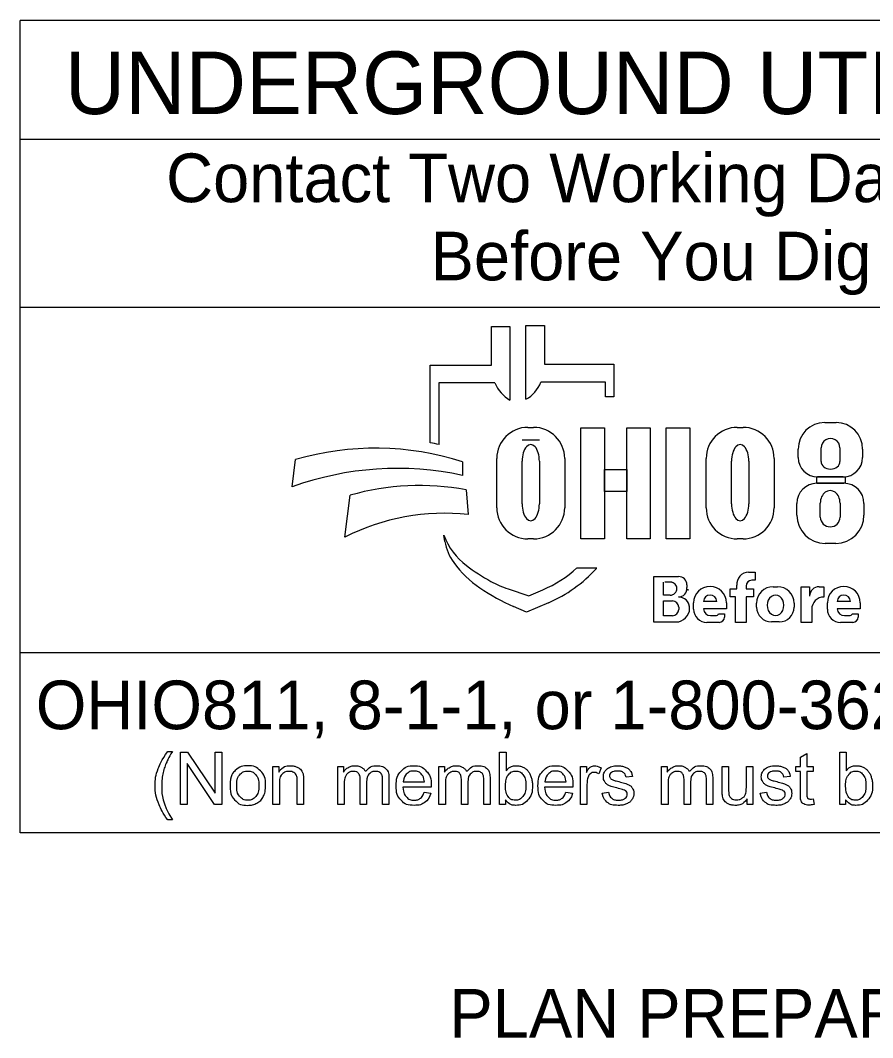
# Model space of a CAD drawing. Extents: x -7.9 to 76.1, y 0 to 22.
# Drawn here: x 46.508 to 48.961, y 2.433 to 5.36 of the extents above; entities that cross this region are included whole.
import ezdxf

# ---------------------------------------------------------------- set-up
doc = ezdxf.new("R2010")
doc.units = 0
doc.layers.add('SH_Data', color=7, linetype='Continuous')
doc.layers.add('SH_Text', color=7, linetype='Continuous')

msp = doc.modelspace()

# ---------------------------------------------------------------- linework, layer by layer
at = {"layer": 'SH_Data'}
for p, q in [((46.5077, 3.0228), (46.5077, 5.3603)), ((50.7577, 5.3603), (46.5077, 5.3603)), ((46.5077, 5.0187), (50.7577, 5.0187)), ((46.5077, 4.5353), (50.7577, 4.5353)), ((50.7577, 3.5406), (46.5077, 3.5406)), ((50.7577, 3.0228), (46.5077, 3.0228))]:
    msp.add_line(p, q, dxfattribs=at)
at = {"layer": 'SH_Text'}
for p, q in [((47.8638, 4.3683), (47.8638, 4.4798)), ((47.8638, 4.4798), (47.9174, 4.4798)), ((47.9174, 4.4798), (47.9174, 4.2677)), ((47.9631, 4.27), (47.9631, 4.4821)), ((47.9631, 4.4821), (48.0167, 4.4821)), ((48.0167, 4.4821), (48.0167, 4.3706)), ((47.6878, 4.1444), (47.6878, 4.3683)), ((47.6878, 4.3683), (47.8638, 4.3683)), ((48.0167, 4.3706), (48.216, 4.3706)), ((48.216, 4.3706), (48.216, 4.2768)), ((47.713, 4.3168), (47.713, 4.14)), ((47.8742, 4.3168), (47.713, 4.3168)), ((48.1927, 4.3192), (48.0063, 4.3192)), ((48.1927, 4.2768), (48.1927, 4.3192)), ((48.216, 4.2768), (48.1927, 4.2768)), ((47.9688, 4.1891), (47.9853, 4.1891)), ((48.5718, 4.1891), (48.5883, 4.1891)), ((48.8233, 4.2031), (48.8561, 4.2031)), ((48.002, 4.1521), (47.9522, 4.1521)), ((48.8132, 4.0911), (48.8132, 4.1304)), ((48.8673, 4.1304), (48.8673, 4.0911)), ((47.8793, 3.9576), (47.8793, 4.0996)), ((48.0748, 4.0996), (48.0748, 3.9576)), ((48.4823, 3.9576), (48.4823, 4.0996)), ((48.6778, 4.0996), (48.6778, 3.9576)), ((48.747, 4.1025), (48.747, 4.1268)), ((48.9324, 4.1268), (48.9324, 4.1025)), ((47.2904, 4.0181), (47.2998, 4.0962)), ((47.7811, 4.0897), (47.7811, 4.0509)), ((47.9522, 3.969), (47.9522, 4.0914)), ((48.002, 4.0914), (48.002, 3.969)), ((48.5552, 3.969), (48.5552, 4.0914)), ((48.605, 4.0914), (48.605, 3.969)), ((48.8764, 4.0465), (48.803, 4.0465)), ((48.8012, 4.0282), (48.8785, 4.0282)), ((47.4423, 3.8736), (47.457, 3.9937)), ((47.7911, 4.0091), (47.7973, 3.9382)), ((48.7433, 3.9363), (48.7433, 3.9703)), ((48.8108, 3.9303), (48.8108, 3.9712)), ((48.8677, 3.9712), (48.8677, 3.9303)), ((48.9364, 3.9703), (48.9364, 3.9363)), ((47.73, 3.8607), (47.7269, 3.8786)), ((47.9853, 3.8682), (47.9688, 3.8682)), ((48.5883, 3.8682), (48.5718, 3.8682)), ((48.8555, 3.8553), (48.8243, 3.8553)), ((48.1103, 3.7848), (48.1677, 3.7848)), ((48.3315, 3.629), (48.3315, 3.7598)), ((48.3315, 3.7598), (48.4027, 3.7598)), ((48.6041, 3.7726), (48.6236, 3.7726)), ((48.6236, 3.7491), (48.6134, 3.7491)), ((48.6236, 3.7726), (48.6236, 3.7496)), ((47.9118, 3.7244), (47.9712, 3.7039)), ((47.9712, 3.7039), (48.0123, 3.7217)), ((48.3595, 3.7063), (48.3595, 3.7432)), ((48.3847, 3.7432), (48.3634, 3.7432)), ((48.4265, 3.736), (48.4265, 3.7281)), ((48.5515, 3.7012), (48.5515, 3.7242)), ((48.5515, 3.7242), (48.5709, 3.7242)), ((48.5709, 3.7242), (48.5709, 3.7346)), ((48.597, 3.7326), (48.597, 3.7242)), ((48.597, 3.7242), (48.6185, 3.7242)), ((48.6185, 3.7242), (48.6185, 3.7012)), ((48.6753, 3.7307), (48.6875, 3.7307)), ((48.7556, 3.6278), (48.7556, 3.7305)), ((48.7556, 3.7305), (48.7801, 3.7305)), ((48.7801, 3.7305), (48.7801, 3.7036)), ((48.8074, 3.7305), (48.8213, 3.7305)), ((48.8213, 3.7305), (48.8213, 3.7009)), ((48.3789, 3.7063), (48.3595, 3.7063)), ((48.3595, 3.6469), (48.3595, 3.6897)), ((48.3595, 3.6897), (48.385, 3.6897)), ((48.5664, 3.7012), (48.5515, 3.7012)), ((48.5664, 3.6278), (48.5664, 3.7012)), ((48.6185, 3.7012), (48.597, 3.7012)), ((48.597, 3.7012), (48.597, 3.6278)), ((47.9652, 3.6569), (47.9279, 3.6734)), ((48.0285, 3.6844), (47.9652, 3.6569)), ((48.4032, 3.6716), (48.4032, 3.6652)), ((48.4345, 3.6687), (48.4345, 3.6684)), ((48.4461, 3.6658), (48.4461, 3.6842)), ((48.5127, 3.6882), (48.4741, 3.6882)), ((48.5406, 3.6666), (48.4742, 3.6666)), ((48.5406, 3.6842), (48.5406, 3.6666)), ((48.6275, 3.6721), (48.6275, 3.6829)), ((48.7353, 3.6829), (48.7353, 3.6721)), ((48.7861, 3.666), (48.7861, 3.6278)), ((48.831, 3.6658), (48.831, 3.6842)), ((48.8976, 3.6882), (48.8591, 3.6882)), ((48.9255, 3.6666), (48.8591, 3.6666)), ((48.9255, 3.6842), (48.9255, 3.6666)), ((48.3848, 3.6469), (48.3595, 3.6469)), ((48.4951, 3.6473), (48.5092, 3.6473)), ((48.5178, 3.6529), (48.5347, 3.6529)), ((48.5347, 3.6529), (48.5347, 3.6431)), ((48.88, 3.6473), (48.8942, 3.6473)), ((48.9027, 3.6529), (48.9196, 3.6529)), ((48.9196, 3.6529), (48.9196, 3.6431)), ((48.3952, 3.629), (48.3315, 3.629)), ((48.5195, 3.6278), (48.4841, 3.6278)), ((48.597, 3.6278), (48.5664, 3.6278)), ((48.6925, 3.6294), (48.6703, 3.6294)), ((48.7861, 3.6278), (48.7556, 3.6278)), ((48.9044, 3.6278), (48.869, 3.6278))]:
    msp.add_line(p, q, dxfattribs=at)
for points in [[(48.1212, 4.1881), (48.1891, 4.1881), (48.1891, 3.8681), (48.1212, 3.8681)], [(48.2533, 4.1881), (48.3213, 4.1881), (48.3213, 3.8681), (48.2533, 3.8681)], [(48.3666, 4.1881), (48.4354, 4.1881), (48.4354, 3.8681), (48.3666, 3.8681)], [(48.1891, 4.0682), (48.2533, 4.0682), (48.2533, 4.0042), (48.1891, 4.0042)], [(48.8009, 4.0465), (48.8825, 4.0465), (48.8825, 4.0281), (48.8009, 4.0281)]]:
    msp.add_lwpolyline(points, close=True, dxfattribs=at)
for points in [[(46.9323, 3.2566), (46.9455, 3.2566)], [(46.9691, 3.1039), (46.9691, 3.2541), (46.9894, 3.2541), (47.0684, 3.1361), (47.0684, 3.2541), (47.0874, 3.2541), (47.0874, 3.1039), (47.0671, 3.1039), (46.9881, 3.2218), (46.9881, 3.1039), (46.9691, 3.1039)], [(47.9045, 3.1039), (47.8875, 3.1039), (47.8875, 3.2541), (47.9059, 3.2541), (47.9059, 3.2006)], [(48.7535, 3.1358), (48.7535, 3.1984), (48.7399, 3.1984), (48.7399, 3.2128), (48.7535, 3.2128), (48.7535, 3.2397), (48.7719, 3.2508), (48.7719, 3.2128), (48.7903, 3.2128), (48.7903, 3.1984), (48.7719, 3.1984), (48.7719, 3.1347)], [(48.8836, 3.1039), (48.8666, 3.1039), (48.8666, 3.2541), (48.885, 3.2541), (48.885, 3.2006)], [(47.2351, 3.1039), (47.2351, 3.2128), (47.2516, 3.2128), (47.2516, 3.1973)], [(47.4215, 3.1039), (47.4215, 3.2128), (47.4379, 3.2128), (47.4379, 3.1974)], [(47.7128, 3.1039), (47.7128, 3.2128), (47.7293, 3.2128), (47.7293, 3.1974)], [(48.1206, 3.1039), (48.1206, 3.2128), (48.1372, 3.2128), (48.1372, 3.1963)], [(48.1797, 3.2093), (48.1732, 3.1922)], [(48.3538, 3.1039), (48.3538, 3.2128), (48.3703, 3.2128), (48.3703, 3.1974)], [(48.5282, 3.1454), (48.5282, 3.2128), (48.5466, 3.2128), (48.5466, 3.1524)], [(48.5978, 3.1545), (48.5978, 3.2128), (48.6163, 3.2128), (48.6163, 3.1039), (48.5998, 3.1039)], [(47.2535, 3.1633), (47.2535, 3.1039), (47.2351, 3.1039)], [(47.3234, 3.1708), (47.3234, 3.1039), (47.305, 3.1039), (47.305, 3.1701)], [(47.5045, 3.1671), (47.5045, 3.1039), (47.4861, 3.1039), (47.4861, 3.1746)], [(47.569, 3.1786), (47.569, 3.1039), (47.5506, 3.1039), (47.5506, 3.1724)], [(47.6101, 3.1687), (47.6709, 3.1687)], [(47.7959, 3.1671), (47.7959, 3.1039), (47.7775, 3.1039), (47.7775, 3.1746)], [(47.8604, 3.1786), (47.8604, 3.1039), (47.8419, 3.1039), (47.8419, 3.1724)], [(48.0181, 3.1687), (48.0788, 3.1687)], [(48.2696, 3.1846), (48.2515, 3.1822)], [(48.4369, 3.1671), (48.4369, 3.1039), (48.4185, 3.1039), (48.4185, 3.1746)], [(48.5014, 3.1786), (48.5014, 3.1039), (48.4829, 3.1039), (48.4829, 3.1724)], [(48.7242, 3.1846), (48.7061, 3.1822)], [(47.4399, 3.1603), (47.4399, 3.1039), (47.4215, 3.1039)], [(47.6902, 3.1536), (47.6091, 3.1536)], [(47.6706, 3.139), (47.6897, 3.1366)], [(47.7313, 3.1603), (47.7313, 3.1039), (47.7128, 3.1039)], [(48.0982, 3.1536), (48.017, 3.1536)], [(48.0786, 3.139), (48.0977, 3.1366)], [(48.139, 3.1609), (48.139, 3.1039), (48.1206, 3.1039)], [(48.1832, 3.1364), (48.2014, 3.1393)], [(48.3723, 3.1603), (48.3723, 3.1039), (48.3538, 3.1039)], [(48.6378, 3.1364), (48.656, 3.1393)], [(47.9045, 3.1175), (47.9045, 3.1039)], [(48.5998, 3.1039), (48.5998, 3.12)], [(48.7903, 3.1203), (48.793, 3.1041)], [(48.8836, 3.1175), (48.8836, 3.1039)], [(46.9455, 3.0597), (46.9323, 3.0597)]]:
    msp.add_lwpolyline(points, dxfattribs=at)
for centre, radius, start, end in [((47.9655, 4.3536), 0.0985, 201.9296, 240.7469), ((47.915, 4.3559), 0.0985, 299.2531, 338.0704), ((47.9688, 4.0996), 0.0895, 90, 180), ((47.9853, 4.0996), 0.0895, 0, 90), ((48.5718, 4.0996), 0.0895, 90, 180), ((48.5883, 4.0996), 0.0895, 0, 90), ((48.8233, 4.1268), 0.0763, 90, 180), ((48.8561, 4.1268), 0.0763, 0, 90), ((47.5299, 3.3101), 0.8191, 72.1402, 106.3144), ((47.5597, 3.3354), 0.8191, 79.2074, 81.0007), ((48.803, 4.1025), 0.056, 180, 270), ((48.8764, 4.1025), 0.056, 270, 0), ((47.593, 3.179), 0.8919, 77.8238, 109.8274), ((47.6569, 3.2894), 0.7322, 79.44, 105.8467), ((48.8012, 3.9703), 0.0579, 90, 180), ((48.8785, 3.9703), 0.0579, 0, 90), ((47.9688, 3.9576), 0.0895, 180, 270), ((47.9853, 3.9576), 0.0895, 270, 0), ((48.5718, 3.9576), 0.0895, 180, 270), ((48.5883, 3.9576), 0.0895, 270, 0), ((47.7289, 3.3061), 0.6357, 83.8248, 116.8021), ((48.8243, 3.9363), 0.081, 180, 270), ((48.8555, 3.9363), 0.081, 270, 0), ((47.9143, 3.9507), 0.2008, 201.0457, 232.5314), ((47.8713, 3.8848), 0.1433, 189.6817, 216.0884), ((48.0049, 3.9822), 0.3088, 216.0884, 235.7167), ((48.1068, 4.2019), 0.5173, 232.5314, 241.794), ((47.8689, 4.0522), 0.3602, 293.4582, 312.0712), ((47.8689, 4.0522), 0.401, 293.4582, 317.8286), ((48.4027, 3.736), 0.0238, 0, 90), ((48.6041, 3.739), 0.0335, 90, 187.5187), ((48.6134, 3.7326), 0.0165, 90, 180), ((48.1714, 4.2265), 0.6044, 235.7167, 246.2325), ((48.0217, 4.0431), 0.3371, 241.794, 250.9821), ((48.3789, 3.725), 0.0187, 270, 2.0582), ((48.3808, 3.7263), 0.0169, 357.8325, 90), ((48.4023, 3.7253), 0.0243, 270, 6.6529), ((48.4129, 3.7238), 0.0175, 347.4023, 0), ((48.4933, 3.6842), 0.0473, 0, 180), ((48.6753, 3.6829), 0.0478, 90, 180), ((48.6875, 3.6829), 0.0478, 0, 90), ((48.807, 3.7036), 0.0269, 89.2449, 180), ((48.8783, 3.6842), 0.0473, 0, 180), ((48.385, 3.6716), 0.0181, 0, 90), ((48.4024, 3.6689), 0.0321, 4.0748, 90), ((48.4934, 3.6872), 0.0193, 2.9632, 177.0368), ((48.821, 3.666), 0.0349, 89.6033, 180), ((48.8783, 3.6872), 0.0193, 2.9632, 177.0368), ((48.3848, 3.6652), 0.0184, 270, 0), ((48.3952, 3.6684), 0.0393, 270, 0), ((48.4016, 3.6687), 0.033, 0, 11.7502), ((48.4841, 3.6658), 0.038, 180, 270), ((48.4951, 3.6683), 0.021, 184.827, 270), ((48.6703, 3.6721), 0.0428, 180, 270), ((48.6925, 3.6721), 0.0428, 270, 0), ((48.869, 3.6658), 0.038, 180, 270), ((48.88, 3.6683), 0.021, 184.827, 270), ((48.5092, 3.6567), 0.00938, 270, 335.9979), ((48.5195, 3.6431), 0.0152, 270, 0), ((48.8942, 3.6567), 0.00938, 270, 335.9979), ((48.9044, 3.6431), 0.0152, 270, 0)]:
    msp.add_arc(centre, radius, start, end, dxfattribs=at)
for centre, major_axis, ratio, start_param, end_param in [((47.9771, 4.0914), (0, 0.0484), 0.514403, 4.712389, 7.853982), ((48.5801, 4.0914), (0, 0.0484), 0.514403, 4.712389, 7.853982), ((48.8402, 4.1304), (0.0271, 0), 0.969373, 0, 3.141593), ((48.8402, 4.0911), (0.0271, 0), 0.818453, 3.141593, 6.283185), ((48.8392, 3.9712), (0, 0.0358), 0.794529, 4.712389, 7.853982), ((47.9771, 3.969), (0, 0.0484), 0.514403, 1.570796, 4.712389), ((48.5801, 3.969), (0, 0.0484), 0.514403, 1.570796, 4.712389), ((48.8392, 3.9303), (0.0284, 0), 0.959837, 3.141593, 6.283185), ((48.6819, 3.6775), (0, 0.029), 0.832186, 4.712389, 7.853982), ((48.6819, 3.6775), (0, 0.0302), 0.797287, 1.570796, 4.712389)]:
    msp.add_ellipse(centre, major_axis=major_axis, ratio=ratio, start_param=start_param, end_param=end_param, dxfattribs=at)
for points in [[(46.9323, 3.0597), (46.9171, 3.079), (46.9065, 3.1048), (46.896, 3.1306), (46.896, 3.1583), (46.896, 3.1826), (46.9038, 3.205), (46.9131, 3.2309), (46.9323, 3.2566)], [(46.9455, 3.2566), (46.9331, 3.2353), (46.9292, 3.2262), (46.9229, 3.212), (46.9193, 3.1967), (46.915, 3.1775), (46.915, 3.1582), (46.915, 3.1089), (46.9455, 3.0597)], [(47.1116, 3.1583), (47.1116, 3.1885), (47.1284, 3.2031), (47.1424, 3.2152), (47.1625, 3.2152), (47.185, 3.2152), (47.1992, 3.2005), (47.2134, 3.1858), (47.2134, 3.1599), (47.2134, 3.1389), (47.2071, 3.1269), (47.2008, 3.1148), (47.1888, 3.1082), (47.1768, 3.1015), (47.1625, 3.1015), (47.1397, 3.1015), (47.1256, 3.1162), (47.1116, 3.1308), (47.1116, 3.1583)], [(47.1306, 3.1583), (47.1306, 3.1374), (47.1397, 3.127), (47.1488, 3.1166), (47.1625, 3.1166), (47.1762, 3.1166), (47.1853, 3.1271), (47.1944, 3.1375), (47.1944, 3.1589), (47.1944, 3.1791), (47.1853, 3.1895), (47.1761, 3.1999), (47.1625, 3.1999), (47.1488, 3.1999), (47.1397, 3.1896), (47.1306, 3.1792), (47.1306, 3.1583)], [(47.2516, 3.1973), (47.2636, 3.2152), (47.2862, 3.2152), (47.2961, 3.2152), (47.3043, 3.2116), (47.3126, 3.2081), (47.3166, 3.2024), (47.3207, 3.1966), (47.3224, 3.1887), (47.3234, 3.1836), (47.3234, 3.1708)], [(47.305, 3.1701), (47.305, 3.1813), (47.3028, 3.1869), (47.3007, 3.1925), (47.2952, 3.1958), (47.2897, 3.1991), (47.2823, 3.1991), (47.2706, 3.1991), (47.262, 3.1917), (47.2535, 3.1842), (47.2535, 3.1633)], [(47.4379, 3.1974), (47.4431, 3.2054), (47.4516, 3.2103), (47.4601, 3.2152), (47.4709, 3.2152), (47.483, 3.2152), (47.4908, 3.2101), (47.4985, 3.2051), (47.5017, 3.1961), (47.5146, 3.2152), (47.5353, 3.2152), (47.5515, 3.2152), (47.5603, 3.2062), (47.569, 3.1972), (47.569, 3.1786)], [(47.4861, 3.1746), (47.4861, 3.1868), (47.4816, 3.193), (47.4771, 3.1991), (47.4668, 3.1991), (47.4591, 3.1991), (47.4524, 3.195), (47.4458, 3.1909), (47.4429, 3.1831), (47.4399, 3.1752), (47.4399, 3.1603)], [(47.5506, 3.1724), (47.5506, 3.1835), (47.5488, 3.1883), (47.547, 3.1932), (47.5423, 3.1962), (47.5375, 3.1991), (47.5312, 3.1991), (47.5197, 3.1991), (47.5121, 3.1915), (47.5045, 3.1839), (47.5045, 3.1671)], [(47.6897, 3.1366), (47.6852, 3.1199), (47.673, 3.1107), (47.6608, 3.1015), (47.6419, 3.1015), (47.618, 3.1015), (47.604, 3.1162), (47.5901, 3.1309), (47.5901, 3.1574), (47.5901, 3.1848), (47.6042, 3.2), (47.6183, 3.2152), (47.6408, 3.2152), (47.6627, 3.2152), (47.6765, 3.2003), (47.6903, 3.1854), (47.6903, 3.1585), (47.6903, 3.1569), (47.6902, 3.1536)], [(47.6709, 3.1687), (47.6696, 3.1825), (47.6639, 3.1894), (47.6551, 3.2), (47.641, 3.2), (47.6283, 3.2), (47.6197, 3.1915), (47.611, 3.183), (47.6101, 3.1687)], [(47.7293, 3.1974), (47.7344, 3.2054), (47.7429, 3.2103), (47.7514, 3.2152), (47.7623, 3.2152), (47.7744, 3.2152), (47.7821, 3.2101), (47.7899, 3.2051), (47.7931, 3.1961), (47.806, 3.2152), (47.8267, 3.2152), (47.8429, 3.2152), (47.8516, 3.2062), (47.8604, 3.1972), (47.8604, 3.1786)], [(47.7775, 3.1746), (47.7775, 3.1868), (47.773, 3.193), (47.7685, 3.1991), (47.7582, 3.1991), (47.7504, 3.1991), (47.7438, 3.195), (47.7372, 3.1909), (47.7342, 3.1831), (47.7313, 3.1752), (47.7313, 3.1603)], [(47.8419, 3.1724), (47.8419, 3.1835), (47.8401, 3.1883), (47.8383, 3.1932), (47.8336, 3.1962), (47.8289, 3.1991), (47.8226, 3.1991), (47.8111, 3.1991), (47.8035, 3.1915), (47.7959, 3.1839), (47.7959, 3.1671)], [(47.9043, 3.1592), (47.9043, 3.1396), (47.9096, 3.1309), (47.9183, 3.1166), (47.9331, 3.1166), (47.9452, 3.1166), (47.954, 3.1271), (47.9628, 3.1376), (47.9628, 3.1584), (47.9628, 3.1798), (47.9544, 3.1899), (47.9459, 3.2), (47.934, 3.2), (47.9219, 3.2), (47.9131, 3.1895), (47.9043, 3.179), (47.9043, 3.1592)], [(47.9059, 3.2006), (47.9176, 3.2152), (47.9357, 3.2152), (47.9458, 3.2152), (47.9547, 3.2111), (47.9637, 3.2071), (47.9695, 3.1997), (47.9752, 3.1924), (47.9785, 3.1821), (47.9818, 3.1717), (47.9818, 3.16), (47.9818, 3.132), (47.968, 3.1168), (47.9541, 3.1015), (47.9348, 3.1015), (47.9155, 3.1015), (47.9045, 3.1175)], [(48.0977, 3.1366), (48.0932, 3.1199), (48.081, 3.1107), (48.0688, 3.1015), (48.0499, 3.1015), (48.026, 3.1015), (48.012, 3.1162), (47.998, 3.1309), (47.998, 3.1574), (47.998, 3.1848), (48.0122, 3.2), (48.0263, 3.2152), (48.0488, 3.2152), (48.0707, 3.2152), (48.0845, 3.2003), (48.0983, 3.1854), (48.0983, 3.1585), (48.0983, 3.1569), (48.0982, 3.1536)], [(48.0788, 3.1687), (48.0776, 3.1825), (48.0719, 3.1894), (48.0631, 3.2), (48.049, 3.2), (48.0363, 3.2), (48.0277, 3.1915), (48.019, 3.183), (48.0181, 3.1687)], [(48.1372, 3.1963), (48.1436, 3.2078), (48.1489, 3.2115), (48.1543, 3.2152), (48.1607, 3.2152), (48.1701, 3.2152), (48.1797, 3.2093)], [(48.1732, 3.1922), (48.1665, 3.1962), (48.1598, 3.1962), (48.1537, 3.1962), (48.149, 3.1925), (48.1442, 3.1889), (48.1421, 3.1824), (48.139, 3.1726), (48.139, 3.1609)], [(48.2515, 3.1822), (48.2503, 3.1906), (48.2444, 3.1953), (48.2385, 3.2), (48.2277, 3.2), (48.215, 3.2), (48.2096, 3.1958), (48.2042, 3.1916), (48.2042, 3.186), (48.2042, 3.1824), (48.2064, 3.1795), (48.2087, 3.1766), (48.2135, 3.1746), (48.2163, 3.1736), (48.2298, 3.1699), (48.2494, 3.1647), (48.2571, 3.1613), (48.2649, 3.158), (48.2693, 3.1517), (48.2737, 3.1453), (48.2737, 3.1359), (48.2737, 3.1267), (48.2684, 3.1186), (48.263, 3.1104), (48.2528, 3.106), (48.2426, 3.1015), (48.2298, 3.1015), (48.2086, 3.1015), (48.1974, 3.1103), (48.1863, 3.1191), (48.1832, 3.1364)], [(48.2014, 3.1393), (48.203, 3.1283), (48.21, 3.1225), (48.217, 3.1166), (48.2297, 3.1166), (48.2424, 3.1166), (48.2486, 3.1218), (48.2547, 3.127), (48.2547, 3.134), (48.2547, 3.1402), (48.2493, 3.1438), (48.2455, 3.1463), (48.2304, 3.1501), (48.2101, 3.1552), (48.2023, 3.1589), (48.1944, 3.1627), (48.1904, 3.1693), (48.1863, 3.1759), (48.1863, 3.1838), (48.1863, 3.1911), (48.1896, 3.1973), (48.193, 3.2035), (48.1987, 3.2076), (48.203, 3.2108), (48.2105, 3.213), (48.2179, 3.2152), (48.2264, 3.2152), (48.2393, 3.2152), (48.2489, 3.2115), (48.2586, 3.2078), (48.2633, 3.2015), (48.2679, 3.1952), (48.2696, 3.1846)], [(48.3703, 3.1974), (48.3754, 3.2054), (48.3839, 3.2103), (48.3924, 3.2152), (48.4033, 3.2152), (48.4154, 3.2152), (48.4231, 3.2101), (48.4309, 3.2051), (48.4341, 3.1961), (48.447, 3.2152), (48.4677, 3.2152), (48.4839, 3.2152), (48.4926, 3.2062), (48.5014, 3.1972), (48.5014, 3.1786)], [(48.4185, 3.1746), (48.4185, 3.1868), (48.414, 3.193), (48.4095, 3.1991), (48.3992, 3.1991), (48.3914, 3.1991), (48.3848, 3.195), (48.3782, 3.1909), (48.3752, 3.1831), (48.3723, 3.1752), (48.3723, 3.1603)], [(48.4829, 3.1724), (48.4829, 3.1835), (48.4811, 3.1883), (48.4793, 3.1932), (48.4746, 3.1962), (48.4699, 3.1991), (48.4636, 3.1991), (48.4521, 3.1991), (48.4445, 3.1915), (48.4369, 3.1839), (48.4369, 3.1671)], [(48.7061, 3.1822), (48.7049, 3.1906), (48.699, 3.1953), (48.6931, 3.2), (48.6823, 3.2), (48.6696, 3.2), (48.6642, 3.1958), (48.6587, 3.1916), (48.6587, 3.186), (48.6587, 3.1824), (48.661, 3.1795), (48.6632, 3.1766), (48.6681, 3.1746), (48.6708, 3.1736), (48.6844, 3.1699), (48.704, 3.1647), (48.7117, 3.1613), (48.7195, 3.158), (48.7239, 3.1517), (48.7283, 3.1453), (48.7283, 3.1359), (48.7283, 3.1267), (48.7229, 3.1186), (48.7175, 3.1104), (48.7074, 3.106), (48.6972, 3.1015), (48.6844, 3.1015), (48.6631, 3.1015), (48.652, 3.1103), (48.6409, 3.1191), (48.6378, 3.1364)], [(48.656, 3.1393), (48.6575, 3.1283), (48.6646, 3.1225), (48.6716, 3.1166), (48.6842, 3.1166), (48.697, 3.1166), (48.7031, 3.1218), (48.7093, 3.127), (48.7093, 3.134), (48.7093, 3.1402), (48.7039, 3.1438), (48.7001, 3.1463), (48.685, 3.1501), (48.6647, 3.1552), (48.6568, 3.1589), (48.649, 3.1627), (48.6449, 3.1693), (48.6409, 3.1759), (48.6409, 3.1838), (48.6409, 3.1911), (48.6442, 3.1973), (48.6475, 3.2035), (48.6533, 3.2076), (48.6576, 3.2108), (48.665, 3.213), (48.6725, 3.2152), (48.681, 3.2152), (48.6938, 3.2152), (48.7035, 3.2115), (48.7132, 3.2078), (48.7178, 3.2015), (48.7224, 3.1952), (48.7242, 3.1846)], [(48.8834, 3.1592), (48.8834, 3.1396), (48.8887, 3.1309), (48.8974, 3.1166), (48.9122, 3.1166), (48.9243, 3.1166), (48.9331, 3.1271), (48.9419, 3.1376), (48.9419, 3.1584), (48.9419, 3.1798), (48.9334, 3.1899), (48.925, 3.2), (48.913, 3.2), (48.901, 3.2), (48.8922, 3.1895), (48.8834, 3.179), (48.8834, 3.1592)], [(48.885, 3.2006), (48.8967, 3.2152), (48.9148, 3.2152), (48.9248, 3.2152), (48.9338, 3.2111), (48.9427, 3.2071), (48.9485, 3.1997), (48.9543, 3.1924), (48.9576, 3.1821), (48.9609, 3.1717), (48.9609, 3.16), (48.9609, 3.132), (48.947, 3.1168), (48.9332, 3.1015), (48.9138, 3.1015), (48.8946, 3.1015), (48.8836, 3.1175)], [(47.6091, 3.1536), (47.6101, 3.1357), (47.6192, 3.1261), (47.6283, 3.1166), (47.642, 3.1166), (47.6521, 3.1166), (47.6593, 3.122), (47.6664, 3.1273), (47.6706, 3.139)], [(48.017, 3.1536), (48.0181, 3.1357), (48.0272, 3.1261), (48.0363, 3.1166), (48.0499, 3.1166), (48.0601, 3.1166), (48.0673, 3.122), (48.0744, 3.1273), (48.0786, 3.139)], [(48.5998, 3.12), (48.5871, 3.1015), (48.5653, 3.1015), (48.5557, 3.1015), (48.5473, 3.1052), (48.539, 3.1089), (48.535, 3.1145), (48.5309, 3.1201), (48.5293, 3.1281), (48.5282, 3.1336), (48.5282, 3.1454)], [(48.5466, 3.1524), (48.5466, 3.138), (48.5477, 3.133), (48.5494, 3.1257), (48.5551, 3.1216), (48.5607, 3.1174), (48.569, 3.1174), (48.5773, 3.1174), (48.5845, 3.1217), (48.5918, 3.1259), (48.5948, 3.1332), (48.5978, 3.1406), (48.5978, 3.1545)], [(48.793, 3.1041), (48.7852, 3.1024), (48.7791, 3.1024), (48.769, 3.1024), (48.7635, 3.1056), (48.758, 3.1088), (48.7557, 3.114), (48.7535, 3.1191), (48.7535, 3.1358)], [(48.7719, 3.1347), (48.7719, 3.1268), (48.7729, 3.1245), (48.7739, 3.1223), (48.776, 3.1209), (48.7782, 3.1196), (48.7823, 3.1196), (48.7854, 3.1196), (48.7903, 3.1203)]]:
    msp.add_open_spline(points, degree=3, dxfattribs=at)

# ---------------------------------------------------------------- texts
for s, height, p in [('UNDERGROUND UTILITIES', 0.18, (46.6359, 5.0906)), ('Contact Two Working Days', 0.14, (46.9274, 4.8371)), ('Before You Dig', 0.14, (47.6886, 4.6121)), ('OHIO811, 8-1-1, or 1-800-362-2764', 0.14, (46.5522, 3.3206)), ('PLAN PREPARED BY:', 0.14, (47.7427, 2.433))]:
    msp.add_text(s, height=height, dxfattribs=at).set_placement(p)

doc.saveas('drawing.dxf')
